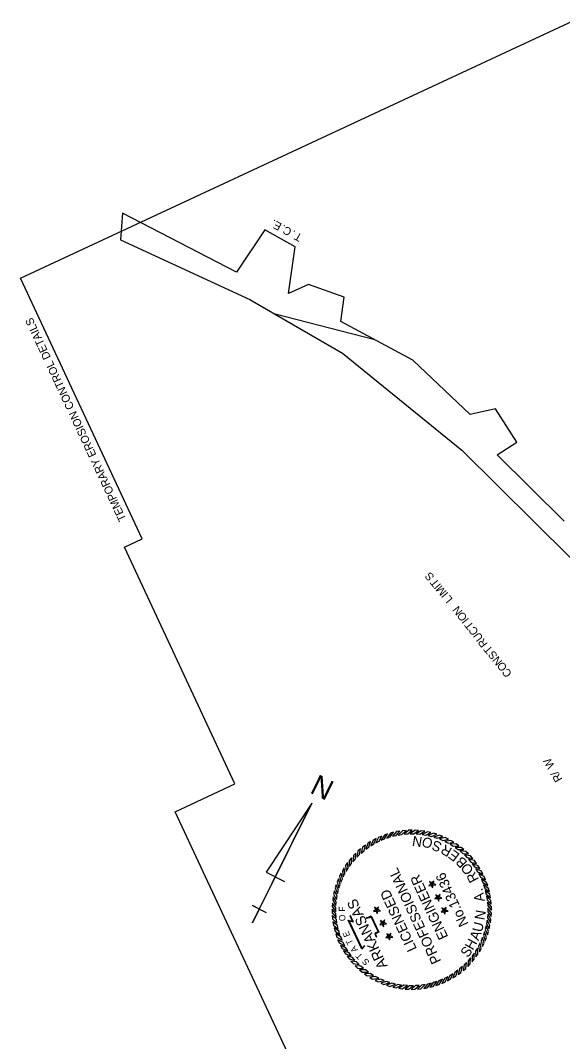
# Model space of a CAD drawing. Extents: x 964229 to 965790, y 1899262 to 1901149.
# Drawn here: x 964229 to 964635, y 1900163 to 1900928 of the extents above; entities that cross this region are included whole.
import ezdxf

# ---------------------------------------------------------------- set-up
doc = ezdxf.new("R2010")
doc.units = 0
for name, color, linetype in [('1', 7, 'Continuous'), ('63', 7, 'Continuous'), ('G-ANNO-SYMB', 7, 'Continuous'), ('NO PLOT', 7, 'Continuous'), ('R_Draft', 7, 'Continuous'), ('R_Horz Alg Annot', 7, 'Continuous')]:
    doc.layers.add(name, color=color, linetype=linetype)

msp = doc.modelspace()

# ---------------------------------------------------------------- linework, layer by layer
at = {"layer": '63'}
for p, q in [((964402.67, 1900252.08), (964447.04, 1900341.7)), ((964447.04, 1900341.7), (964412.84, 1900289.96)), ((964447.04, 1900341.7), (964412.91, 1900272.76)), ((964412.84, 1900289.96), (964426.63, 1900283.14)), ((964402.67, 1900252.08), (964412.91, 1900272.76)), ((964407.79, 1900262.42), (964402.62, 1900264.98)), ((964402.62, 1900264.98), (964412.96, 1900259.86)), ((964402.67, 1900252.08), (964407.79, 1900262.42))]:
    msp.add_line(p, q, dxfattribs=at)
at = {"layer": 'G-ANNO-SYMB'}
for points in [[(964495.16, 1900315.17), (964492.89, 1900313.97), (964491.14, 1900309.74), (964493.51, 1900311.18)], [(964499.42, 1900317.1), (964497.07, 1900316.08), (964494.99, 1900312.01), (964497.46, 1900313.26)], [(964503.83, 1900318.69), (964501.4, 1900317.86), (964499.01, 1900313.97), (964501.57, 1900315.02)], [(964508.34, 1900319.94), (964505.86, 1900319.3), (964503.17, 1900315.6), (964505.81, 1900316.45)], [(964512.94, 1900320.82), (964510.42, 1900320.38), (964507.45, 1900316.9), (964510.14, 1900317.54)], [(964517.6, 1900321.34), (964515.04, 1900321.1), (964511.81, 1900317.87), (964514.55, 1900318.29)], [(964522.28, 1900321.5), (964519.72, 1900321.46), (964516.24, 1900318.49), (964519, 1900318.7)], [(964526.96, 1900321.28), (964524.4, 1900321.45), (964520.7, 1900318.76), (964523.47, 1900318.75)], [(964531.61, 1900320.7), (964529.07, 1900321.07), (964525.17, 1900318.68), (964527.93, 1900318.45)], [(964536.2, 1900319.76), (964533.69, 1900320.32), (964529.62, 1900318.25), (964532.36, 1900317.8)], [(964540.7, 1900318.46), (964538.25, 1900319.22), (964534.02, 1900317.47), (964536.71, 1900316.81)], [(964545.08, 1900316.81), (964542.7, 1900317.76), (964538.35, 1900316.34), (964540.98, 1900315.48)], [(964549.32, 1900314.82), (964547.02, 1900315.95), (964542.57, 1900314.89), (964545.13, 1900313.82)], [(964483.45, 1900307.45), (964481.52, 1900305.75), (964480.8, 1900301.24), (964482.77, 1900303.19)], [(964487.14, 1900310.33), (964485.09, 1900308.79), (964484.02, 1900304.34), (964486.14, 1900306.13)], [(964491.05, 1900312.9), (964488.89, 1900311.53), (964487.47, 1900307.18), (964489.72, 1900308.8)], [(964553.4, 1900312.51), (964551.19, 1900313.82), (964546.67, 1900313.1), (964549.14, 1900311.83)], [(964557.27, 1900309.88), (964555.18, 1900311.36), (964550.62, 1900311), (964552.98, 1900309.54)], [(964560.94, 1900306.96), (964558.96, 1900308.59), (964554.39, 1900308.59), (964556.62, 1900306.96)], [(964476.78, 1900300.87), (964475.15, 1900298.89), (964475.15, 1900294.32), (964476.78, 1900296.56)], [(964479.99, 1900304.29), (964478.2, 1900302.45), (964477.84, 1900297.89), (964479.65, 1900299.99)], [(964564.35, 1900303.76), (964562.51, 1900305.54), (964557.95, 1900305.9), (964560.06, 1900304.1)], [(964567.51, 1900300.3), (964565.82, 1900302.22), (964561.3, 1900302.94), (964563.25, 1900300.97)], [(964570.39, 1900296.6), (964568.85, 1900298.65), (964564.4, 1900299.72), (964566.2, 1900297.61)], [(964471.23, 1900293.33), (964469.93, 1900291.12), (964470.64, 1900286.61), (964471.91, 1900289.07)], [(964473.86, 1900297.21), (964472.38, 1900295.11), (964472.74, 1900290.55), (964474.2, 1900292.91)], [(964572.97, 1900292.69), (964571.59, 1900294.86), (964567.25, 1900296.27), (964568.87, 1900294.02)], [(964575.23, 1900288.59), (964574.03, 1900290.86), (964569.81, 1900292.6), (964571.25, 1900290.24)], [(964466.93, 1900285.02), (964465.99, 1900282.63), (964467.4, 1900278.28), (964468.26, 1900280.92)], [(964468.92, 1900289.26), (964467.79, 1900286.96), (964468.86, 1900282.51), (964469.93, 1900285.07)], [(964577.16, 1900284.32), (964576.15, 1900286.68), (964572.07, 1900288.75), (964573.32, 1900286.28)], [(964578.76, 1900279.92), (964577.93, 1900282.34), (964574.03, 1900284.73), (964575.08, 1900282.17)], [(964465.28, 1900280.63), (964464.53, 1900278.18), (964466.28, 1900273.96), (964466.93, 1900276.65)], [(964537.16, 1900280.99), (964536.14, 1900281.19), (964534.69, 1900279.84), (964536.66, 1900280.08)], [(964537.16, 1900280.99), (964537.04, 1900282.03), (964535.3, 1900282.99), (964536.14, 1900281.19)], [(964537.16, 1900280.99), (964536.66, 1900280.08), (964537.5, 1900278.29), (964537.87, 1900280.23)], [(964537.16, 1900280.99), (964538.11, 1900281.43), (964538.49, 1900283.38), (964537.04, 1900282.03)], [(964537.16, 1900280.99), (964537.87, 1900280.23), (964539.84, 1900280.47), (964538.11, 1900281.43)], [(964580, 1900275.4), (964579.36, 1900277.88), (964575.67, 1900280.57), (964576.51, 1900277.93)], [(964463.04, 1900271.54), (964462.68, 1900269), (964465.07, 1900265.11), (964465.29, 1900267.87)], [(964463.98, 1900276.13), (964463.42, 1900273.63), (964465.5, 1900269.55), (964465.94, 1900272.29)], [(964541.77, 1900271.11), (964540.75, 1900271.3), (964539.3, 1900269.95), (964541.27, 1900270.19)], [(964541.77, 1900271.11), (964541.65, 1900272.14), (964539.91, 1900273.1), (964540.75, 1900271.3)], [(964541.77, 1900271.11), (964541.27, 1900270.19), (964542.11, 1900268.4), (964542.49, 1900270.34)], [(964541.77, 1900271.11), (964542.72, 1900271.55), (964543.1, 1900273.49), (964541.65, 1900272.14)], [(964541.77, 1900271.11), (964542.49, 1900270.34), (964544.45, 1900270.58), (964542.72, 1900271.55)], [(964580.89, 1900270.8), (964580.45, 1900273.33), (964576.97, 1900276.3), (964577.61, 1900273.6)], [(964581.41, 1900266.14), (964581.17, 1900268.7), (964577.93, 1900271.93), (964578.36, 1900269.19)], [(964462.25, 1900262.22), (964462.28, 1900259.65), (964465.25, 1900256.17), (964465.05, 1900258.94)], [(964462.46, 1900266.9), (964462.3, 1900264.34), (964464.98, 1900260.64), (964464.99, 1900263.41)], [(964495.76, 1900261.69), (964494.74, 1900261.88), (964493.29, 1900260.53), (964495.26, 1900260.77)], [(964495.76, 1900261.69), (964495.64, 1900262.72), (964493.9, 1900263.68), (964494.74, 1900261.88)], [(964495.76, 1900261.69), (964495.26, 1900260.77), (964496.09, 1900258.98), (964496.47, 1900260.92)], [(964495.76, 1900261.69), (964496.71, 1900262.13), (964497.08, 1900264.07), (964495.64, 1900262.72)], [(964495.76, 1900261.69), (964496.47, 1900260.92), (964498.44, 1900261.17), (964496.71, 1900262.13)], [(964546.39, 1900261.22), (964545.36, 1900261.42), (964543.91, 1900260.07), (964545.88, 1900260.31)], [(964546.39, 1900261.22), (964546.26, 1900262.25), (964544.53, 1900263.21), (964545.36, 1900261.42)], [(964546.39, 1900261.22), (964547.33, 1900261.66), (964547.71, 1900263.6), (964546.26, 1900262.25)], [(964546.39, 1900261.22), (964547.1, 1900260.46), (964549.06, 1900260.7), (964547.33, 1900261.66)], [(964581.56, 1900261.46), (964581.52, 1900264.03), (964578.55, 1900267.5), (964578.76, 1900264.74)], [(964581.35, 1900256.78), (964581.51, 1900259.34), (964578.82, 1900263.04), (964578.81, 1900260.27)], [(964462.4, 1900257.53), (964462.64, 1900254.98), (964465.87, 1900251.75), (964465.45, 1900254.49)], [(964500.37, 1900251.8), (964500.25, 1900252.83), (964498.51, 1900253.79), (964499.35, 1900252)], [(964500.37, 1900251.8), (964501.32, 1900252.24), (964501.69, 1900254.18), (964500.25, 1900252.83)], [(964546.39, 1900261.22), (964545.88, 1900260.31), (964546.72, 1900258.51), (964547.1, 1900260.46)], [(964579.83, 1900247.55), (964580.39, 1900250.05), (964578.31, 1900254.12), (964577.87, 1900251.39)], [(964580.77, 1900252.13), (964581.13, 1900254.67), (964578.74, 1900258.57), (964578.52, 1900255.81)], [(964462.92, 1900252.88), (964463.36, 1900250.35), (964466.84, 1900247.38), (964466.2, 1900250.08)], [(964463.81, 1900248.28), (964464.44, 1900245.79), (964468.14, 1900243.11), (964467.29, 1900245.74)], [(964500.37, 1900251.8), (964499.35, 1900252), (964497.9, 1900250.65), (964499.87, 1900250.89)], [(964500.37, 1900251.8), (964499.87, 1900250.89), (964500.71, 1900249.09), (964501.08, 1900251.04)], [(964500.37, 1900251.8), (964501.08, 1900251.04), (964503.05, 1900251.28), (964501.32, 1900252.24)], [(964578.53, 1900243.04), (964579.28, 1900245.5), (964577.53, 1900249.72), (964576.88, 1900247.03)], [(964465.05, 1900243.76), (964465.88, 1900241.33), (964469.78, 1900238.95), (964468.72, 1900241.51)], [(964466.64, 1900239.36), (964467.66, 1900237), (964471.73, 1900234.93), (964470.48, 1900237.4)], [(964504.98, 1900241.91), (964503.96, 1900242.11), (964502.51, 1900240.76), (964504.48, 1900241)], [(964504.98, 1900241.91), (964504.86, 1900242.95), (964503.12, 1900243.91), (964503.96, 1900242.11)], [(964504.98, 1900241.91), (964504.48, 1900241), (964505.32, 1900239.2), (964505.69, 1900241.15)], [(964504.98, 1900241.91), (964505.93, 1900242.35), (964506.31, 1900244.3), (964504.86, 1900242.95)], [(964504.98, 1900241.91), (964505.69, 1900241.15), (964507.66, 1900241.39), (964505.93, 1900242.35)], [(964574.89, 1900234.42), (964576.02, 1900236.72), (964574.95, 1900241.17), (964573.88, 1900238.61)], [(964576.88, 1900238.66), (964577.82, 1900241.05), (964576.41, 1900245.39), (964575.54, 1900242.76)], [(964468.58, 1900235.09), (964469.78, 1900232.82), (964474, 1900231.07), (964472.56, 1900233.44)], [(964470.84, 1900230.99), (964472.21, 1900228.82), (964476.56, 1900227.41), (964474.94, 1900229.66)], [(964569.95, 1900226.47), (964571.42, 1900228.57), (964571.06, 1900233.12), (964569.61, 1900230.77)], [(964572.57, 1900230.35), (964573.88, 1900232.55), (964573.17, 1900237.07), (964571.9, 1900234.6)], [(964473.42, 1900227.08), (964474.96, 1900225.03), (964479.4, 1900223.96), (964477.61, 1900226.07)], [(964476.29, 1900223.38), (964477.99, 1900221.46), (964482.51, 1900220.74), (964480.55, 1900222.71)], [(964563.82, 1900219.39), (964565.61, 1900221.23), (964565.97, 1900225.79), (964564.16, 1900223.69)], [(964567.02, 1900222.81), (964568.66, 1900224.78), (964568.66, 1900229.36), (964567.02, 1900227.12)], [(964479.45, 1900219.92), (964481.29, 1900218.13), (964485.85, 1900217.78), (964483.75, 1900219.58)], [(964482.87, 1900216.72), (964484.85, 1900215.08), (964489.42, 1900215.08), (964487.18, 1900216.72)], [(964552.75, 1900210.77), (964554.92, 1900212.15), (964556.33, 1900216.5), (964554.09, 1900214.88)], [(964556.66, 1900213.35), (964558.72, 1900214.89), (964559.78, 1900219.34), (964557.67, 1900217.55)], [(964560.36, 1900216.23), (964562.29, 1900217.93), (964563, 1900222.44), (964561.04, 1900220.49)], [(964486.53, 1900213.8), (964488.63, 1900212.32), (964493.19, 1900212.68), (964490.83, 1900214.13)], [(964490.41, 1900211.17), (964492.62, 1900209.86), (964497.13, 1900210.58), (964494.67, 1900211.84)], [(964494.48, 1900208.85), (964496.79, 1900207.72), (964501.23, 1900208.79), (964498.68, 1900209.86)], [(964498.72, 1900206.87), (964501.11, 1900205.92), (964505.46, 1900207.33), (964502.83, 1900208.2)], [(964535.46, 1900203.74), (964537.95, 1900204.38), (964540.64, 1900208.08), (964538, 1900207.23)], [(964539.98, 1900204.98), (964542.41, 1900205.81), (964544.8, 1900209.71), (964542.23, 1900208.66)], [(964544.39, 1900206.58), (964546.74, 1900207.6), (964548.82, 1900211.67), (964546.34, 1900210.42)], [(964548.65, 1900208.51), (964550.92, 1900209.71), (964552.67, 1900213.94), (964550.3, 1900212.5)], [(964503.11, 1900205.22), (964505.56, 1900204.46), (964509.79, 1900206.21), (964507.09, 1900206.87)], [(964507.61, 1900203.92), (964510.11, 1900203.36), (964514.19, 1900205.43), (964511.45, 1900205.87)], [(964512.2, 1900202.97), (964514.74, 1900202.61), (964518.64, 1900205), (964515.87, 1900205.23)], [(964516.85, 1900202.39), (964519.41, 1900202.23), (964523.11, 1900204.92), (964520.33, 1900204.93)], [(964521.53, 1900202.18), (964524.09, 1900202.22), (964527.57, 1900205.19), (964524.8, 1900204.98)], [(964526.21, 1900202.33), (964528.76, 1900202.58), (964532, 1900205.81), (964529.26, 1900205.38)], [(964530.86, 1900202.86), (964533.39, 1900203.3), (964536.36, 1900206.77), (964533.66, 1900206.13)]]:
    msp.add_lwpolyline(points, close=True, dxfattribs=at)
for points in [[(964486.7, 1900234.88), (964484.56, 1900232.34), (964474.38, 1900254.15), (964477.51, 1900253.39), (964476.8, 1900254.86), (964476.21, 1900256.1), (964475.77, 1900257.39)], [(964486.41, 1900235.12), (964484.65, 1900233.04), (964475.06, 1900253.59), (964478.21, 1900252.83), (964477.15, 1900255.03), (964476.56, 1900256.24), (964476.13, 1900257.52)], [(964487.69, 1900255.91), (964488.28, 1900255.62), (964488.94, 1900255.74), (964490.18, 1900256.16), (964491.36, 1900256.71), (964496.71, 1900245.22), (964495.02, 1900244.44), (964494.31, 1900244.11), (964494.44, 1900243.21), (964495.19, 1900241.61), (964494.97, 1900241.26)], [(964487.86, 1900256.25), (964488.34, 1900256.02), (964488.85, 1900256.11), (964490.03, 1900256.51), (964491.54, 1900257.21), (964497.22, 1900245.04), (964495.18, 1900244.09), (964494.73, 1900243.88), (964494.81, 1900243.32), (964495.62, 1900241.58), (964495.29, 1900241.06)]]:
    msp.add_lwpolyline(points, dxfattribs=at)
at = {"layer": 'NO PLOT'}
msp.add_lwpolyline([(964845.11, 1899262.24), (964344.7, 1900335.36), (964389.48, 1900356.24), (964306.73, 1900533.69), (964319.96, 1900539.86), (964228.89, 1900735.17), (964643.21, 1900928.38), (964770.42, 1900655.58), (964700.63, 1900623.04), (964880.25, 1900237.86), (964950.03, 1900270.4), (965070.98, 1900011.03), (965017.24, 1899985.98), (965162.05, 1899675.42), (965215.79, 1899700.48), (965317.44, 1899482.49)], close=True, dxfattribs=at)
msp.add_lwpolyline([(964845.11, 1899262.24), (964344.7, 1900335.36), (964389.48, 1900356.24), (964306.73, 1900533.69), (964319.96, 1900539.86), (964228.89, 1900735.17), (964643.21, 1900928.38), (964770.42, 1900655.58), (964700.63, 1900623.04), (964880.25, 1900237.86), (964950.03, 1900270.4), (965070.98, 1900011.03), (965017.24, 1899985.98), (965162.05, 1899675.42), (965215.79, 1899700.48), (965317.44, 1899482.49)], close=True, dxfattribs=at)
msp.add_lwpolyline([(964845.11, 1899262.24), (964344.7, 1900335.36), (964389.48, 1900356.24), (964306.73, 1900533.69), (964319.96, 1900539.86), (964228.89, 1900735.17), (964643.21, 1900928.38), (964770.42, 1900655.58), (964700.63, 1900623.04), (964880.25, 1900237.86), (964950.03, 1900270.4), (965070.98, 1900011.03), (965017.24, 1899985.98), (965162.05, 1899675.42), (965215.79, 1899700.48), (965317.44, 1899482.49)], close=True, dxfattribs=at)
msp.add_lwpolyline([(964845.11, 1899262.24), (964344.7, 1900335.36), (964389.48, 1900356.24), (964306.73, 1900533.69), (964319.96, 1900539.86), (964228.89, 1900735.17), (964643.21, 1900928.38), (964770.42, 1900655.58), (964700.63, 1900623.04), (964880.25, 1900237.86), (964950.03, 1900270.4), (965070.98, 1900011.03), (965017.24, 1899985.98), (965162.05, 1899675.42), (965215.79, 1899700.48), (965317.44, 1899482.49)], close=True, dxfattribs=at)
msp.add_lwpolyline([(964635.92, 1900553.17), (964585.88, 1900602.76), (964600.62, 1900612.22), (964584.73, 1900637.4), (964565.52, 1900633.1), (964522.79, 1900673.69), (964468.84, 1900702.84), (964471.22, 1900721.02), (964444.63, 1900730.34), (964429.55, 1900723.82), (964434.5, 1900758.72), (964411.98, 1900771.49), (964390.55, 1900739.77), (964305.32, 1900783.82), (964303.72, 1900763.94), (964400.68, 1900719.15), (964433.31, 1900700.23), (964470.07, 1900679.1), (964559.33, 1900606.42), (964640.41, 1900525.78)], dxfattribs=at)
at = {"layer": 'R_Horz Alg Annot'}
msp.add_line((964494.27, 1900689.1), (964419.58, 1900708.19), dxfattribs=at)

# ---------------------------------------------------------------- texts
at = {"layer": '1'}
msp.add_text('TEMPORARY EROSION CONTROL DETAILS', height=6, rotation=115, dxfattribs=at).set_placement((964308.32, 1900554.65))
at = {"layer": '63'}
msp.add_text('N', height=15.38, rotation=333.65549, dxfattribs=at).set_placement((964444.84, 1900349.94))
at = {"layer": 'G-ANNO-SYMB'}
for s, height, rotation, p in [('N', 7.5, 171.10067, (964530.16, 1900316.15)), ('O', 7.5, 159.77573, (964538.48, 1900314.29)), ('S', 7.5, 158.48784, (964545.16, 1900311.72)), ('R', 7.5, 150.65967, (964552.7, 1900307.63)), ('E', 7.5, 142.83149, (964558.39, 1900303.28)), ('B', 7.5, 133.88501, (964564.04, 1900297.56)), ('PROFESSIONAL', 7.5, 115, (964544.02, 1900223.29)), ('O', 7.5, 126.42961, (964568.66, 1900291.42)), ('ENGINEER', 7.5, 115, (964549.35, 1900241.54)), ('No.13436', 7.47, 115, (964564.55, 1900251.24)), ('R', 7.5, 118.22866, (964572.35, 1900284.67)), ('.', 7.5, 106.30002, (964575.37, 1900275.94)), ('ARKANSAS', 7.747, 115, (964503.96, 1900219.68)), ('LICENSED', 7.5, 115, (964525.86, 1900232.55)), ('A', 7.5, 98.09908, (964576.51, 1900268.33)), ('F', 4.75, 90.36282, (964472.04, 1900260.48)), ('N', 7.5, 79.93262, (964576.2, 1900253.76)), ('O', 4.75, 96.2218, (964472.48, 1900253.62)), ('E', 4.75, 111.67203, (964475.88, 1900242.49)), ('U', 7.5, 75.90262, (964574.33, 1900244.55)), ('T', 4.75, 116.47887, (964478.31, 1900236.92)), ('H', 7.5, 60.61905, (964567.68, 1900231.04)), ('A', 7.5, 68.44722, (964571.88, 1900238.25)), ('A', 4.75, 123.67877, (964481.76, 1900231.76)), ('S', 7.5, 53.16364, (964563.8, 1900225.46)), ('T', 4.75, 131.90148, (964485.56, 1900227.18)), ('S', 4.75, 134.77256, (964490.57, 1900222.85))]:
    msp.add_text(s, height=height, rotation=rotation, dxfattribs=at).set_placement(p)
at = {"layer": 'R_Draft'}
for s, rotation, p in [('E', 151.66279, (964425.09, 1900775.81)), ('.', 151.66279, (964420.35, 1900778.37)), ('.', 151.66279, (964427.67, 1900774.42)), ('C', 151.66279, (964432.66, 1900771.73)), ('T', 151.66279, (964440.39, 1900767.56)), ('.', 151.66279, (964435.24, 1900770.34)), ('S', 129.90046, (964539.19, 1900511.37)), ('T', 129.5737, (964542.92, 1900506.86)), ('I', 129.5737, (964544.19, 1900505.33)), ('M', 129.86193, (964548.32, 1900500.4)), ('I', 129.86193, (964549.59, 1900498.88)), ('L', 128.49437, (964552.9, 1900494.63)), ('N', 128.44984, (964560.26, 1900485.58)), ('O', 127.88388, (964563.87, 1900480.97)), ('I', 127.76002, (964565.08, 1900479.39)), ('T', 128.50533, (964568.73, 1900474.81)), ('C', 128.9602, (964572.3, 1900470.41)), ('U', 126.79603, (964575.72, 1900465.77)), ('R', 126.74567, (964579.11, 1900461.22)), ('T', 130.66004, (964583.02, 1900456.85)), ('S', 129.05345, (964586.55, 1900452.41)), ('N', 129.09817, (964590.11, 1900448.01)), ('O', 127.42654, (964593.74, 1900443.41)), ('C', 128.39334, (964597.23, 1900438.94)), ('W', 120.18332, (964629.09, 1900369.66)), ('/', 120.18332, (964632.04, 1900364.6)), ('R', 120.18332, (964634.89, 1900359.7))]:
    msp.add_text(s, height=6, rotation=rotation, dxfattribs=at).set_placement(p)

doc.saveas('drawing.dxf')
